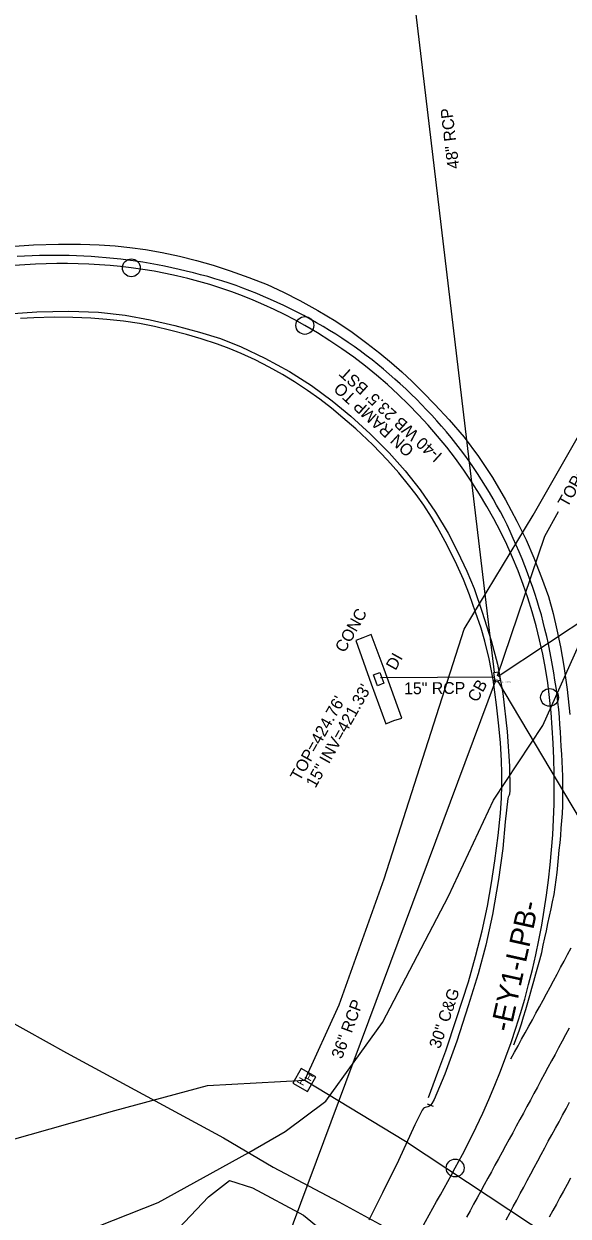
# Model space of a CAD drawing. Extents: x 2074109 to 2077820, y 741079 to 746031.
# Drawn here: x 2075438.5 to 2075622.1, y 743570.1 to 743972 of the extents above; entities that cross this region are included whole.
import ezdxf

# ---------------------------------------------------------------- set-up
doc = ezdxf.new("R2010")
doc.units = 0
for name, color, linetype in [('Exist Horizontal Alignment', 7, 'Continuous'), ('Exist Horizontal Alignment Direction Label', 7, 'Continuous'), ('Exist Horizontal Alignment Point', 7, 'Continuous'), ('Exist Roads Curbs', 7, 'Continuous'), ('Exist Roads Curbs Text', 7, 'Continuous'), ('Exist Roads EOP', 7, 'Continuous'), ('Exist Roads EOP Text', 7, 'Continuous'), ('Exist Roads EOT', 7, 'Continuous'), ('Exist Structure Minor Catch Basin', 7, 'Continuous'), ('Exist Structure Minor Catch Basin Leader', 7, 'Continuous'), ('Exist Structure Minor Catch Basin Text', 7, 'Continuous'), ('Exist Structure Minor Catch Basin Top Elevation', 7, 'Continuous'), ('Exist Structure Minor Drop Inlet', 7, 'Continuous'), ('Exist Structure Minor Drop Inlet Text', 7, 'Continuous'), ('Exist Structure Minor Drop Inlet Top Elevation', 7, 'Continuous'), ('Exist Structure Minor Paved Ditch or Gutter', 7, 'Continuous'), ('Exist Structure Minor Paved Ditch or Gutter Text', 7, 'Continuous'), ('Exist Structure Minor Pipes RCP 15 Inch', 7, 'Continuous'), ('Exist Structure Minor Pipes RCP 15 Inch Invert', 7, 'Continuous'), ('Exist Structure Minor Pipes RCP 15 Inch Text', 7, 'Continuous'), ('Exist Structure Minor Pipes RCP 36 Inch', 7, 'Continuous'), ('Exist Structure Minor Pipes RCP 36 Inch Text', 7, 'Continuous'), ('Exist Structure Minor Pipes RCP 42 Inch', 7, 'Continuous'), ('Exist Structure Minor Pipes RCP 48 Inch', 7, 'Continuous'), ('Exist Structure Minor Pipes RCP 48 Inch Text', 7, 'Continuous'), ('Exist Structure Minor Storm Sewer Line Cogo Comment', 7, 'Continuous'), ('Exist Structure Minor Storm Sewer Line Cogo Number', 7, 'Continuous'), ('Exist Structure Minor Storm Sewer Line Cogo Point CELL', 7, 'Continuous'), ('Exist Utilities Gas UG Line SUE LOS B', 7, 'Continuous'), ('Exist Utilities Power Hand Hole CELL', 7, 'Continuous'), ('Exist Utilities Power UG Cable SUE LOS B', 7, 'Continuous'), ('Exist Utilities Telephone UG FO SUE LOS B', 7, 'Continuous'), ('Exist Vegetation Hedge Row', 7, 'Continuous')]:
    doc.layers.add(name, color=color, linetype=linetype)

msp = doc.modelspace()

# ---------------------------------------------------------------- linework, layer by layer
at = {"layer": 'Exist Horizontal Alignment'}
for centre, radius, start, end in [((2065746.77, 748969.72), 11283.45, 330.581241, 339.398504), ((2075451.51, 743703.89), 187.28, 82.8656, 118.0163), ((2075455.13, 743732.81), 158.13, 60.3897, 82.8656), ((2075451.7, 743726.77), 165.08, 6.3176, 60.3897), ((2075350.75, 743715.6), 266.64, 331.0001, 6.3176), ((2065715.23, 749056.64), 11283.45, 330.581241, 331.000067)]:
    msp.add_arc(centre, radius, start, end, dxfattribs=at)
at = {"layer": 'Exist Horizontal Alignment Point'}
for centre in [(2075474.77, 743889.72), (2075533.27, 743870.3), (2075615.78, 743744.94), (2075583.96, 743586.33)]:
    msp.add_circle(centre, 3, dxfattribs=at)
at = {"layer": 'Exist Roads Curbs'}
msp.add_lwpolyline([(2075574.96, 743610.04), (2075578.15, 743618.6), (2075580.78, 743625.84), (2075584.45, 743636.72), (2075588.46, 743649.05), (2075590.84, 743657.56), (2075593.02, 743666.3), (2075594.82, 743674.6), (2075596.23, 743682.46), (2075597.36, 743689.88), (2075598.44, 743698.38), (2075599.22, 743705.95), (2075599.58, 743710.96), (2075599.73, 743715.4), (2075599.74, 743719.4), (2075599.6, 743723.65), (2075599.23, 743729.64), (2075598.71, 743735.3), (2075597.85, 743742.47), (2075596.72, 743750.96), (2075595.42, 743757.89), (2075593.95, 743763.88), (2075592.67, 743768.32), (2075590.86, 743773.66), (2075588.76, 743779.54), (2075586.73, 743784.65), (2075583.94, 743790.8), (2075580.57, 743797.5), (2075577.94, 743802.4), (2075575.97, 743805.73), (2075573.4, 743809.68), (2075570.77, 743813.37), (2075568.26, 743816.6), (2075564.93, 743820.58), (2075561.12, 743824.92), (2075556.16, 743830.07), (2075550.45, 743835.44), (2075546.12, 743839.19), (2075542.26, 743842.38), (2075538.28, 743845.48), (2075534.14, 743848.41), (2075529.76, 743851.28), (2075525.69, 743853.75), (2075521.29, 743856.2), (2075516.58, 743858.66), (2075511.86, 743860.87), (2075507.74, 743862.57), (2075503.81, 743864), (2075498.35, 743865.78), (2075493.35, 743867.27), (2075488.1, 743868.65), (2075482.57, 743869.95), (2075477.57, 743870.97), (2075472.14, 743871.77), (2075466.55, 743872.34), (2075461.09, 743872.76), (2075455.1, 743873.01), (2075448.71, 743873.04), (2075441.94, 743872.85), (2075437.43, 743872.63)], dxfattribs=at)
at = {"layer": 'Exist Roads EOP'}
msp.add_line((2075576.63, 743607.03), (2075574.62, 743607.85), dxfattribs=at)
for points in [[(2075433.76, 743896.94), (2075441.84, 743897.42), (2075450.25, 743897.68), (2075457.61, 743897.7), (2075463.95, 743897.49), (2075469.27, 743897.1), (2075474.25, 743896.55), (2075479.56, 743895.86), (2075485.15, 743894.94), (2075490.96, 743893.68), (2075496.77, 743892.19), (2075502.34, 743890.58), (2075508.08, 743888.73), (2075514.39, 743886.5), (2075520.62, 743884.05), (2075526.11, 743881.52), (2075531.55, 743878.69), (2075537.64, 743875.34), (2075543.75, 743871.69), (2075549.25, 743868), (2075554.18, 743864.37), (2075558.57, 743860.96), (2075562.5, 743857.73), (2075566.03, 743854.63), (2075569.45, 743851.43), (2075573.05, 743847.87), (2075577.11, 743843.67), (2075581.92, 743838.54), (2075586.99, 743832.64), (2075591.87, 743826.14), (2075596.53, 743819.1), (2075600.93, 743811.57), (2075604.8, 743804.29), (2075607.85, 743798), (2075610.49, 743791.95), (2075613.12, 743785.38), (2075615.4, 743778.92), (2075617.02, 743773.18), (2075618.27, 743767.7), (2075619.46, 743761.99), (2075620.59, 743755.5), (2075621.67, 743747.65), (2075622.59, 743739.15)], [(2075431.62, 743874.09), (2075442.88, 743874.91), (2075453.73, 743875.1), (2075463.69, 743874.74), (2075472.67, 743873.72), (2075481.08, 743872.21), (2075489.48, 743870.31), (2075497.75, 743868.08), (2075504.86, 743865.87), (2075511.76, 743863.11), (2075519.84, 743859.22), (2075528.08, 743854.75), (2075535.48, 743850.05), (2075542.45, 743844.89), (2075548.75, 743839.73), (2075555.27, 743833.77), (2075561.74, 743827.37), (2075567.12, 743821.29), (2075572.19, 743814.95), (2075577.31, 743807.4), (2075581.61, 743800.31), (2075584.8, 743794.1), (2075587.91, 743787.53), (2075590.37, 743781.61), (2075593.08, 743773.65), (2075596.08, 743764.06), (2075598.24, 743756.15), (2075600.01, 743746.29), (2075601.54, 743733.48), (2075602.3, 743721.74), (2075602.43, 743714.32), (2075602.39, 743713.38), (2075602.3, 743712.6), (2075602.23, 743712.27), (2075602.14, 743711.98), (2075602.05, 743711.73), (2075601.82, 743711.27), (2075601.7, 743710.87), (2075600.86, 743702.99), (2075600.01, 743694.04), (2075598.58, 743683.53), (2075596.59, 743671.8), (2075594.33, 743661.48), (2075591.74, 743651.72), (2075588.39, 743640.99), (2075584.48, 743629.1), (2075580.46, 743618), (2075576.87, 743609.4), (2075576.11, 743608.1), (2075575.75, 743607.63), (2075575.41, 743607.28), (2075575.09, 743607.05), (2075574.78, 743606.94), (2075574.24, 743606.84), (2075573.8, 743606.72), (2075573.62, 743606.65), (2075573.46, 743606.58), (2075573.33, 743606.51), (2075573.23, 743606.43), (2075573.13, 743606.31), (2075572.84, 743605.86), (2075570.38, 743600.87), (2075564.83, 743588.9), (2075559.5, 743577.98), (2075554.8, 743568.73)]]:
    msp.add_lwpolyline(points, dxfattribs=at)
at = {"layer": 'Exist Roads EOT'}
for points in [[(2075603.77, 743627.87), (2075604.65, 743630.21), (2075605.52, 743632.55), (2075606.29, 743634.93), (2075607.01, 743637.32), (2075607.74, 743639.72), (2075608.46, 743642.11), (2075609.19, 743644.5), (2075609.86, 743646.91), (2075610.53, 743649.32), (2075611.2, 743651.72), (2075611.87, 743654.13), (2075612.54, 743656.54), (2075613.16, 743658.96), (2075613.68, 743661.4), (2075614.21, 743663.85), (2075614.73, 743666.29), (2075615.25, 743668.73), (2075615.77, 743671.18), (2075616.28, 743673.63), (2075616.79, 743676.07), (2075617.31, 743678.52), (2075617.7, 743680.99), (2075618, 743683.47), (2075618.31, 743685.95), (2075618.58, 743688.43), (2075618.83, 743690.92), (2075619.08, 743693.41), (2075619.33, 743695.9), (2075619.54, 743698.39), (2075619.75, 743700.88), (2075619.97, 743703.37), (2075620.18, 743705.86), (2075620.23, 743708.36), (2075620.23, 743710.86), (2075620.23, 743713.36), (2075620.24, 743715.86), (2075620.24, 743718.36), (2075620.13, 743720.86), (2075620, 743723.35), (2075619.88, 743725.85), (2075619.75, 743728.35), (2075619.61, 743730.84), (2075619.44, 743733.34), (2075619.26, 743735.83), (2075619.09, 743738.32), (2075618.86, 743740.81), (2075618.61, 743743.3), (2075618.35, 743745.79), (2075617.98, 743748.26), (2075617.61, 743750.73), (2075617.23, 743753.2), (2075616.76, 743755.66), (2075616.3, 743758.12), (2075615.85, 743760.57), (2075615.4, 743763.03), (2075614.84, 743765.47), (2075614.24, 743767.9), (2075613.65, 743770.32), (2075613.03, 743772.75), (2075612.32, 743775.14), (2075611.62, 743777.54), (2075610.81, 743779.91), (2075610, 743782.27), (2075609.18, 743784.63), (2075608.3, 743786.97), (2075607.42, 743789.31), (2075606.54, 743791.65), (2075605.59, 743793.96), (2075604.57, 743796.25), (2075603.56, 743798.53), (2075602.54, 743800.81), (2075601.44, 743803.06), (2075600.32, 743805.3), (2075599.19, 743807.52), (2075597.95, 743809.69), (2075596.72, 743811.87), (2075595.48, 743814.04), (2075594.17, 743816.17), (2075592.83, 743818.28), (2075591.48, 743820.38), (2075590.1, 743822.46), (2075588.68, 743824.52), (2075587.19, 743826.53), (2075585.71, 743828.54), (2075584.18, 743830.52), (2075582.64, 743832.49), (2075581.03, 743834.4), (2075579.4, 743836.3), (2075577.78, 743838.2), (2075576.09, 743840.03), (2075574.35, 743841.84), (2075572.62, 743843.64), (2075570.87, 743845.42), (2075569.1, 743847.19), (2075567.28, 743848.9), (2075565.45, 743850.6), (2075563.58, 743852.25), (2075561.69, 743853.9), (2075559.81, 743855.54), (2075557.87, 743857.12), (2075555.93, 743858.69), (2075553.96, 743860.22), (2075551.95, 743861.71), (2075549.94, 743863.2), (2075547.87, 743864.59), (2075545.78, 743865.97), (2075543.68, 743867.33), (2075541.55, 743868.63), (2075539.42, 743869.93), (2075537.26, 743871.19), (2075535.09, 743872.43), (2075532.91, 743873.64), (2075530.68, 743874.77), (2075528.45, 743875.91), (2075526.21, 743877), (2075523.95, 743878.07), (2075521.67, 743879.09), (2075519.38, 743880.09), (2075517.09, 743881.08), (2075514.76, 743881.99), (2075512.42, 743882.87), (2075510.07, 743883.72), (2075507.72, 743884.57), (2075505.34, 743885.31), (2075502.95, 743886.03), (2075500.56, 743886.75), (2075498.14, 743887.39), (2075495.73, 743888.03), (2075493.31, 743888.65), (2075490.87, 743889.2), (2075488.44, 743889.76), (2075486, 743890.31), (2075483.55, 743890.76), (2075481.09, 743891.19), (2075478.63, 743891.63), (2075476.16, 743891.98), (2075473.68, 743892.34), (2075471.2, 743892.63), (2075468.72, 743892.88), (2075466.24, 743893.14), (2075463.75, 743893.34), (2075461.26, 743893.54), (2075458.77, 743893.7), (2075456.27, 743893.79), (2075453.78, 743893.88), (2075451.28, 743893.92), (2075448.79, 743893.93), (2075446.29, 743893.93), (2075443.79, 743893.84), (2075441.3, 743893.75), (2075438.81, 743893.63), (2075436.31, 743893.49)], [(2075602.76, 743623.14), (2075603.97, 743625.34), (2075605.17, 743627.53), (2075606.37, 743629.72), (2075607.58, 743631.91), (2075608.78, 743634.1), (2075609.99, 743636.29), (2075611.19, 743638.48), (2075612.39, 743640.67), (2075613.6, 743642.86), (2075614.8, 743645.05), (2075615.98, 743647.25), (2075617.16, 743649.46), (2075618.33, 743651.67), (2075619.51, 743653.87), (2075620.68, 743656.08), (2075621.85, 743658.29), (2075623.03, 743660.5)], [(2075622.35, 743633.43), (2075621.17, 743631.22), (2075619.98, 743629.02), (2075618.8, 743626.82), (2075617.62, 743624.62), (2075616.43, 743622.42), (2075615.25, 743620.22), (2075614.07, 743618.02), (2075612.88, 743615.81), (2075611.7, 743613.61), (2075610.51, 743611.41), (2075609.33, 743609.21), (2075608.15, 743607.01), (2075606.95, 743604.81), (2075605.76, 743602.62), (2075604.56, 743600.42), (2075603.36, 743598.23), (2075602.16, 743596.04), (2075600.96, 743593.84), (2075599.77, 743591.65), (2075598.57, 743589.45), (2075597.37, 743587.26), (2075596.17, 743585.07), (2075594.97, 743582.87), (2075593.77, 743580.68), (2075592.58, 743578.49), (2075591.38, 743576.29), (2075590.18, 743574.1), (2075588.98, 743571.9), (2075587.79, 743569.71)], [(2075601.16, 743568.9), (2075602.34, 743571.1), (2075603.52, 743573.31), (2075604.7, 743575.51), (2075605.89, 743577.71), (2075607.07, 743579.92), (2075608.25, 743582.12), (2075609.43, 743584.32), (2075610.61, 743586.53), (2075611.79, 743588.73), (2075612.97, 743590.93), (2075614.15, 743593.14), (2075615.35, 743595.33), (2075616.56, 743597.52), (2075617.77, 743599.7), (2075618.97, 743601.89), (2075620.16, 743604.09), (2075621.35, 743606.29), (2075622.54, 743608.49)], [(2075622.86, 743582.94), (2075621.67, 743580.74), (2075620.48, 743578.55), (2075619.28, 743576.35), (2075618.09, 743574.15), (2075616.89, 743571.96), (2075615.7, 743569.76)]]:
    msp.add_lwpolyline(points, dxfattribs=at)
at = {"layer": 'Exist Structure Minor Catch Basin'}
msp.add_lwpolyline([(2075597.45, 743750.35), (2075597.01, 743753.38), (2075598.64, 743753.61), (2075599.08, 743750.59)], close=True, dxfattribs=at)
at = {"layer": 'Exist Structure Minor Catch Basin Leader'}
msp.add_lwpolyline([(2075598.28, 743752.16), (2075614.14, 743799.24), (2075618.82, 743807.59)], dxfattribs=at)
at = {"layer": 'Exist Structure Minor Drop Inlet'}
msp.add_lwpolyline([(2075558.58, 743753.33), (2075559.94, 743749.68), (2075557.82, 743748.89), (2075556.46, 743752.53)], close=True, dxfattribs=at)
at = {"layer": 'Exist Structure Minor Paved Ditch or Gutter'}
msp.add_lwpolyline([(2075550.46, 743764.16), (2075555.66, 743749.5), (2075560.62, 743736.02), (2075563.26, 743737.11), (2075565.94, 743737.99), (2075560.07, 743754.43), (2075555.67, 743766.09), (2075552.82, 743765.04), (2075550.46, 743764.16)], dxfattribs=at)
at = {"layer": 'Exist Structure Minor Pipes RCP 15 Inch'}
for p, q in [((2075664.78, 743796.02), (2075598.45, 743752.02)), ((2075558.82, 743751.61), (2075597.23, 743751.87))]:
    msp.add_line(p, q, dxfattribs=at)
at = {"layer": 'Exist Structure Minor Pipes RCP 36 Inch'}
msp.add_line((2075597.45, 743750.35), (2075502.89, 743497.01), dxfattribs=at)
at = {"layer": 'Exist Structure Minor Pipes RCP 42 Inch'}
msp.add_line((2075598.26, 743750.47), (2075665.52, 743637.23), dxfattribs=at)
at = {"layer": 'Exist Structure Minor Pipes RCP 48 Inch'}
msp.add_line((2075542.08, 744215.86), (2075597.15, 743753.38), dxfattribs=at)
at = {"layer": 'Exist Structure Minor Storm Sewer Line Cogo Point CELL'}
msp.add_lwpolyline([(2075597.35, 743750.82), (2075597.35, 743750.21), (2075597.35, 743750.52), (2075597.65, 743750.52), (2075597.05, 743750.52)], dxfattribs=at)
msp.add_circle((2075597.35, 743750.52), 0.234, dxfattribs=at)
at = {"layer": 'Exist Utilities Gas UG Line SUE LOS B'}
msp.add_lwpolyline([(2074897.58, 743757.1), (2074956.84, 743725.22), (2074996.2, 743704.08), (2075050.45, 743674.88), (2075080.67, 743659.46), (2075090.86, 743658.12), (2075109.88, 743660.14), (2075124.59, 743663.58), (2075131.23, 743666.4), (2075141.19, 743667.79), (2075156.06, 743671.95), (2075162.28, 743678.01), (2075191.07, 743728.63), (2075213.69, 743756.53), (2075345.93, 743683.17), (2075411.71, 743648.08), (2075452.87, 743625.17), (2075505.8, 743596.52), (2075522.65, 743586.63), (2075544.69, 743574.93), (2075774.64, 743449.58)], dxfattribs=at)
at = {"layer": 'Exist Utilities Power Hand Hole CELL'}
msp.add_line((2075533.26, 743615.97), (2075533.26, 743615.97), dxfattribs=at)
msp.add_lwpolyline([(2075534.2, 743612.07), (2075537.01, 743617.08), (2075531.99, 743619.89), (2075529.18, 743614.88), (2075534.2, 743612.07)], dxfattribs=at)
at = {"layer": 'Exist Utilities Power UG Cable SUE LOS B'}
for points in [[(2075533.27, 743615.97), (2075544.83, 743641.27), (2075560.03, 743683.75), (2075587, 743767.88), (2075610.31, 743806.32), (2075628.28, 743837.76), (2075630.55, 743844.53), (2075638.42, 743862.98), (2075655.91, 743905.71), (2075673.35, 743941.84), (2075685.65, 743966.62), (2075697.58, 743994.92), (2075714.14, 744036.7), (2075720.97, 744058.18), (2075730.51, 744093.2), (2075744.47, 744129.88), (2075758.43, 744135.59)], [(2075178.8, 743440.68), (2075189.03, 743445.79), (2075192.49, 743448.49), (2075211.79, 743457.77), (2075230.06, 743465.49), (2075235.37, 743473.58), (2075235.47, 743473.59), (2075242.16, 743485.05), (2075256.29, 743509.76), (2075263.78, 743521.99), (2075280.5, 743553.12), (2075288.46, 743567.04), (2075314.59, 743587.39), (2075340.56, 743579.6), (2075397.17, 743587.17), (2075433.19, 743595.47), (2075469.17, 743605.66), (2075500.45, 743614.1), (2075533.26, 743615.97)], [(2075533.27, 743615.97), (2075567.2, 743595.41), (2075714.24, 743498.15), (2075756.41, 743472.15), (2075744.73, 743436.84), (2075735.98, 743400.81), (2075736.7, 743379.57), (2075744.38, 743367.05), (2075761.28, 743352.67), (2075771.54, 743346.58), (2075788.66, 743330.79), (2075794.6, 743320.93)]]:
    msp.add_lwpolyline(points, dxfattribs=at)
at = {"layer": 'Exist Utilities Telephone UG FO SUE LOS B'}
msp.add_lwpolyline([(2075448.92, 743560.88), (2075483.77, 743574.68), (2075514.44, 743591.53), (2075526.61, 743598.64), (2075540.34, 743608.88), (2075559.45, 743635.38), (2075581.73, 743677.96), (2075596.93, 743710.3), (2075613.54, 743735.45), (2075627.1, 743765.82), (2075647.45, 743807.65)], dxfattribs=at)
at = {"layer": 'Exist Vegetation Hedge Row'}
msp.add_lwpolyline([(2075402.68, 743542.14), (2075423.02, 743528.44), (2075436.01, 743520.98), (2075443.55, 743516.96), (2075447.92, 743517.04), (2075454.88, 743525.04), (2075482.7, 743557.52), (2075500.81, 743576.63), (2075507.91, 743582.11), (2075515.67, 743579.69), (2075532.87, 743570.38), (2075538.46, 743565.8), (2075539.89, 743562.14), (2075534.48, 743550.51), (2075517.86, 743518.61), (2075511.56, 743513.56)], dxfattribs=at)

# ---------------------------------------------------------------- texts
at = {"layer": 'Exist Horizontal Alignment Direction Label'}
msp.add_text('-EY1-LPB-', height=7, rotation=77.4753, dxfattribs=at).set_placement((2075602.6, 743631.91))
at = {"layer": 'Exist Roads Curbs Text'}
msp.add_text('30" C&G', height=4, rotation=71.3295, dxfattribs=at).set_placement((2075578.81, 743626.29))
at = {"layer": 'Exist Roads EOP Text'}
for s, p in [("I-40 WB 23.5' BST", (2075579.88, 743826.79)), ('ON RAMP TO', (2075570.37, 743828.6))]:
    msp.add_text(s, height=4, rotation=137.6169, dxfattribs=at).set_placement(p)
at = {"layer": 'Exist Structure Minor Catch Basin Text'}
msp.add_text('CB', height=4, rotation=60.742, dxfattribs=at).set_placement((2075591.36, 743743.03))
at = {"layer": 'Exist Structure Minor Catch Basin Top Elevation'}
msp.add_text("TOP=426.37'", height=4, rotation=60.7411, dxfattribs=at).set_placement((2075621.82, 743808.69))
at = {"layer": 'Exist Structure Minor Drop Inlet Text'}
msp.add_text('DI', height=4, rotation=60.7411, dxfattribs=at).set_placement((2075563.86, 743753.78))
at = {"layer": 'Exist Structure Minor Drop Inlet Top Elevation'}
msp.add_text("TOP=424.76'", height=4, rotation=60.7411, dxfattribs=at).set_placement((2075531.58, 743716.46))
at = {"layer": 'Exist Structure Minor Paved Ditch or Gutter Text'}
msp.add_text('CONC', height=4, rotation=60.742, dxfattribs=at).set_placement((2075546.69, 743759.74))
at = {"layer": 'Exist Structure Minor Pipes RCP 15 Inch Invert'}
msp.add_text('15" INV=421.33\'', height=4, rotation=60.7411, dxfattribs=at).set_placement((2075536.84, 743714.14))
at = {"layer": 'Exist Structure Minor Pipes RCP 15 Inch Text'}
msp.add_text('15" RCP', height=4, rotation=0.3837, dxfattribs=at).set_placement((2075566.75, 743745.99))
at = {"layer": 'Exist Structure Minor Pipes RCP 36 Inch Text'}
msp.add_text('36" RCP', height=4, rotation=69.5317, dxfattribs=at).set_placement((2075545.79, 743622.82))
at = {"layer": 'Exist Structure Minor Pipes RCP 48 Inch Text'}
msp.add_text('48" RCP', height=4, rotation=96.7903, dxfattribs=at).set_placement((2075585.38, 743923.3))
at = {"layer": 'Exist Structure Minor Storm Sewer Line Cogo Comment'}
msp.add_text('CANNOTGETINVERTORPIPESIZE', height=0.25, dxfattribs=at).set_placement((2075597.6, 743750.02))
at = {"layer": 'Exist Structure Minor Storm Sewer Line Cogo Number'}
msp.add_text('2186', height=0.25, dxfattribs=at).set_placement((2075597.6, 743750.77))
at = {"layer": 'Exist Utilities Power Hand Hole CELL'}
for p in [(2075532.62, 743613.86), (2075535.2, 743615.35)]:
    msp.add_text('H', height=2.5, rotation=60.7411, dxfattribs=at).set_placement(p)

doc.saveas('drawing.dxf')
